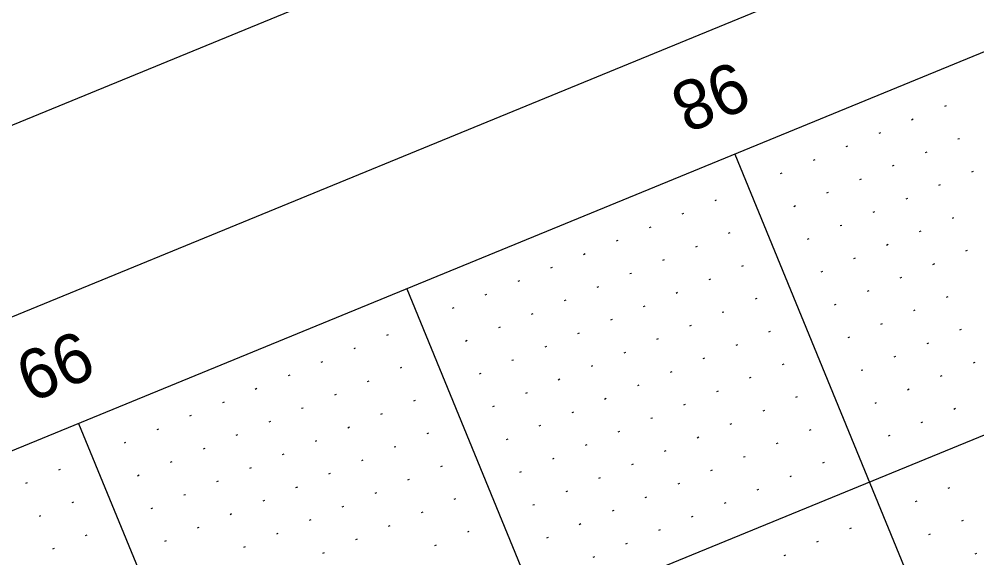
# Model space of a CAD drawing. Extents: x 2148770 to 2150891, y 142633 to 144465.
# Drawn here: x 2149616.7 to 2149751.7, y 143966.2 to 144042.2 of the extents above; entities that cross this region are included whole.
import ezdxf

# ---------------------------------------------------------------- set-up
doc = ezdxf.new("R2010")
doc.units = 0
for name, color, linetype in [('SHT_Plan_Profile_Sheet_Sta_Txt', 7, 'Continuous'), ('SHT_Plot_Shape_Half', 7, 'Continuous'), ('SHT_Profile_Grid_Major', 7, 'Continuous'), ('SHT_Profile_Grid_Minor', 7, 'Continuous'), ('SHT_Sheet_Border', 7, 'Continuous')]:
    doc.layers.add(name, color=color, linetype=linetype)

msp = doc.modelspace()

# ---------------------------------------------------------------- linework, layer by layer
at = {"layer": 'SHT_Plot_Shape_Half'}
msp.add_lwpolyline([(2150799.14, 143324.02), (2149226.52, 142678.36), (2148808.74, 143695.93), (2150381.36, 144341.59)], close=True, dxfattribs=at)
at = {"layer": 'SHT_Profile_Grid_Major'}
for p, q in [((2150326.3, 144218.99), (2148869.31, 143620.81)), ((2149717.57, 144023.12), (2149890.38, 143602.22)), ((2149671.32, 144004.13), (2149844.13, 143583.23)), ((2149625.07, 143985.14), (2149797.88, 143564.24))]:
    msp.add_line(p, q, dxfattribs=at)
at = {"layer": 'SHT_Profile_Grid_Minor'}
for p, q in [((2149747.34, 144029.94), (2149747.11, 144029.84)), ((2149742.72, 144028.04), (2149742.48, 144027.94)), ((2149738.09, 144026.14), (2149737.86, 144026.05)), ((2149733.46, 144024.24), (2149733.23, 144024.15)), ((2149749.24, 144025.31), (2149749.01, 144025.22)), ((2149744.61, 144023.41), (2149744.38, 144023.32)), ((2149728.84, 144022.34), (2149728.61, 144022.25)), ((2149739.99, 144021.52), (2149739.76, 144021.42)), ((2149724.21, 144020.44), (2149723.98, 144020.35)), ((2149751.14, 144020.69), (2149750.91, 144020.59)), ((2149735.36, 144019.62), (2149735.13, 144019.52)), ((2149746.51, 144018.79), (2149746.28, 144018.69)), ((2149730.74, 144017.72), (2149730.51, 144017.62)), ((2149714.96, 144016.65), (2149714.73, 144016.55)), ((2149741.89, 144016.89), (2149741.66, 144016.8)), ((2149710.34, 144014.75), (2149710.11, 144014.65)), ((2149726.11, 144015.82), (2149725.88, 144015.72)), ((2149737.26, 144014.99), (2149737.03, 144014.9)), ((2149748.41, 144014.16), (2149748.18, 144014.07)), ((2149705.71, 144012.85), (2149705.48, 144012.75)), ((2149732.64, 144013.09), (2149732.41, 144013)), ((2149743.79, 144012.26), (2149743.56, 144012.17)), ((2149701.09, 144010.95), (2149700.86, 144010.85)), ((2149716.86, 144012.02), (2149716.63, 144011.93)), ((2149728.01, 144011.19), (2149727.78, 144011.1)), ((2149712.24, 144010.12), (2149712.01, 144010.03)), ((2149739.16, 144010.37), (2149738.93, 144010.27)), ((2149750.31, 144009.54), (2149750.08, 144009.44)), ((2149696.46, 144009.05), (2149696.23, 144008.95)), ((2149707.61, 144008.22), (2149707.38, 144008.13)), ((2149734.54, 144008.47), (2149734.31, 144008.37)), ((2149691.84, 144007.15), (2149691.61, 144007.06)), ((2149718.76, 144007.39), (2149718.53, 144007.3)), ((2149745.69, 144007.64), (2149745.45, 144007.54)), ((2149702.99, 144006.32), (2149702.76, 144006.23)), ((2149714.14, 144005.5), (2149713.9, 144005.4)), ((2149729.91, 144006.57), (2149729.68, 144006.47)), ((2149741.06, 144005.74), (2149740.83, 144005.65)), ((2149687.21, 144005.25), (2149686.98, 144005.16)), ((2149698.36, 144004.42), (2149698.13, 144004.33)), ((2149682.59, 144003.35), (2149682.35, 144003.26)), ((2149709.51, 144003.6), (2149709.28, 144003.5)), ((2149720.66, 144002.77), (2149720.43, 144002.67)), ((2149736.44, 144003.84), (2149736.2, 144003.75)), ((2149747.59, 144003.01), (2149747.35, 144002.92)), ((2149677.96, 144001.45), (2149677.73, 144001.36)), ((2149693.74, 144002.53), (2149693.5, 144002.43)), ((2149704.89, 144001.7), (2149704.65, 144001.6)), ((2149731.81, 144001.94), (2149731.58, 144001.85)), ((2149689.11, 144000.63), (2149688.88, 144000.53)), ((2149716.04, 144000.87), (2149715.8, 144000.78)), ((2149742.96, 144001.11), (2149742.73, 144001.02)), ((2149684.49, 143998.73), (2149684.25, 143998.63)), ((2149700.26, 143999.8), (2149700.03, 143999.7)), ((2149711.41, 143998.97), (2149711.18, 143998.88)), ((2149738.33, 143999.22), (2149738.1, 143999.12)), ((2149668.71, 143997.66), (2149668.48, 143997.56)), ((2149695.63, 143997.9), (2149695.4, 143997.8)), ((2149722.56, 143998.14), (2149722.33, 143998.05)), ((2149733.71, 143997.32), (2149733.48, 143997.22)), ((2149749.48, 143998.39), (2149749.25, 143998.29)), ((2149679.86, 143996.83), (2149679.63, 143996.73)), ((2149691.01, 143996), (2149690.78, 143995.91)), ((2149706.78, 143997.07), (2149706.55, 143996.98)), ((2149717.93, 143996.25), (2149717.7, 143996.15)), ((2149744.86, 143996.49), (2149744.63, 143996.39)), ((2149664.08, 143995.76), (2149663.85, 143995.66)), ((2149702.16, 143995.17), (2149701.93, 143995.08)), ((2149740.23, 143994.59), (2149740, 143994.5)), ((2149659.46, 143993.86), (2149659.23, 143993.76)), ((2149686.38, 143994.1), (2149686.15, 143994.01)), ((2149697.53, 143993.27), (2149697.3, 143993.18)), ((2149713.31, 143994.35), (2149713.08, 143994.25)), ((2149724.46, 143993.52), (2149724.23, 143993.42)), ((2149751.38, 143993.76), (2149751.15, 143993.67)), ((2149654.83, 143991.96), (2149654.6, 143991.86)), ((2149670.61, 143993.03), (2149670.38, 143992.94)), ((2149681.76, 143992.2), (2149681.53, 143992.11)), ((2149708.68, 143992.45), (2149708.45, 143992.35)), ((2149735.61, 143992.69), (2149735.38, 143992.6)), ((2149746.76, 143991.86), (2149746.53, 143991.77)), ((2149665.98, 143991.13), (2149665.75, 143991.04)), ((2149692.91, 143991.38), (2149692.68, 143991.28)), ((2149704.06, 143990.55), (2149703.83, 143990.45)), ((2149719.83, 143991.62), (2149719.6, 143991.52)), ((2149650.21, 143990.06), (2149649.98, 143989.96)), ((2149661.36, 143989.23), (2149661.13, 143989.14)), ((2149688.28, 143989.48), (2149688.05, 143989.38)), ((2149715.21, 143989.72), (2149714.98, 143989.63)), ((2149742.13, 143989.97), (2149741.9, 143989.87)), ((2149645.58, 143988.16), (2149645.35, 143988.07)), ((2149672.51, 143988.4), (2149672.28, 143988.31)), ((2149699.43, 143988.65), (2149699.2, 143988.55)), ((2149710.58, 143987.82), (2149710.35, 143987.73)), ((2149726.36, 143988.89), (2149726.13, 143988.8)), ((2149737.51, 143988.07), (2149737.28, 143987.97)), ((2149656.73, 143987.33), (2149656.5, 143987.24)), ((2149667.88, 143986.51), (2149667.65, 143986.41)), ((2149683.66, 143987.58), (2149683.43, 143987.48)), ((2149694.81, 143986.75), (2149694.58, 143986.66)), ((2149721.73, 143986.99), (2149721.5, 143986.9)), ((2149748.66, 143987.24), (2149748.43, 143987.14)), ((2149640.96, 143986.26), (2149640.73, 143986.17)), ((2149652.11, 143985.43), (2149651.88, 143985.34)), ((2149705.96, 143985.92), (2149705.73, 143985.83)), ((2149717.11, 143985.1), (2149716.88, 143985)), ((2149744.03, 143985.34), (2149743.8, 143985.25)), ((2149636.33, 143984.36), (2149636.1, 143984.27)), ((2149663.26, 143984.61), (2149663.03, 143984.51)), ((2149674.41, 143983.78), (2149674.18, 143983.68)), ((2149690.18, 143984.85), (2149689.95, 143984.76)), ((2149701.33, 143984.02), (2149701.1, 143983.93)), ((2149728.26, 143984.27), (2149728.03, 143984.17)), ((2149631.71, 143982.46), (2149631.48, 143982.37)), ((2149647.48, 143983.54), (2149647.25, 143983.44)), ((2149658.63, 143982.71), (2149658.4, 143982.61)), ((2149685.56, 143982.95), (2149685.33, 143982.86)), ((2149712.48, 143983.2), (2149712.25, 143983.1)), ((2149723.63, 143982.37), (2149723.4, 143982.27)), ((2149739.41, 143983.44), (2149739.17, 143983.35)), ((2149642.86, 143981.64), (2149642.63, 143981.54)), ((2149669.78, 143981.88), (2149669.55, 143981.79)), ((2149696.71, 143982.12), (2149696.48, 143982.03)), ((2149707.86, 143981.3), (2149707.62, 143981.2)), ((2149638.23, 143979.74), (2149638, 143979.64)), ((2149654.01, 143980.81), (2149653.78, 143980.71)), ((2149665.16, 143979.98), (2149664.93, 143979.89)), ((2149692.08, 143980.23), (2149691.85, 143980.13)), ((2149719.01, 143980.47), (2149718.77, 143980.38)), ((2149730.16, 143979.64), (2149729.92, 143979.55)), ((2149622.46, 143978.67), (2149622.23, 143978.57)), ((2149649.38, 143978.91), (2149649.15, 143978.81)), ((2149676.31, 143979.15), (2149676.07, 143979.06)), ((2149687.46, 143978.33), (2149687.22, 143978.23)), ((2149703.23, 143979.4), (2149703, 143979.3)), ((2149714.38, 143978.57), (2149714.15, 143978.48)), ((2149633.61, 143977.84), (2149633.38, 143977.74)), ((2149644.76, 143977.01), (2149644.52, 143976.92)), ((2149660.53, 143978.08), (2149660.3, 143977.99)), ((2149671.68, 143977.26), (2149671.45, 143977.16)), ((2149698.61, 143977.5), (2149698.37, 143977.4)), ((2149725.53, 143977.74), (2149725.3, 143977.65)), ((2149617.83, 143976.77), (2149617.6, 143976.67)), ((2149655.91, 143976.18), (2149655.67, 143976.09)), ((2149693.98, 143975.6), (2149693.75, 143975.51)), ((2149709.76, 143976.67), (2149709.52, 143976.58)), ((2149720.9, 143975.84), (2149720.67, 143975.75)), ((2149747.83, 143976.09), (2149747.6, 143975.99)), ((2149640.13, 143975.11), (2149639.9, 143975.02)), ((2149651.28, 143974.28), (2149651.05, 143974.19)), ((2149667.06, 143975.36), (2149666.82, 143975.26)), ((2149678.2, 143974.53), (2149677.97, 143974.43)), ((2149705.13, 143974.77), (2149704.9, 143974.68)), ((2149624.36, 143974.04), (2149624.12, 143973.95)), ((2149635.51, 143973.21), (2149635.27, 143973.12)), ((2149662.43, 143973.46), (2149662.2, 143973.36)), ((2149689.35, 143973.7), (2149689.12, 143973.61)), ((2149716.28, 143973.95), (2149716.05, 143973.85)), ((2149743.2, 143974.19), (2149742.97, 143974.1)), ((2149619.73, 143972.14), (2149619.5, 143972.05)), ((2149646.65, 143972.39), (2149646.42, 143972.29)), ((2149657.8, 143971.56), (2149657.57, 143971.46)), ((2149673.58, 143972.63), (2149673.35, 143972.53)), ((2149700.5, 143972.87), (2149700.27, 143972.78)), ((2149711.65, 143972.05), (2149711.42, 143971.95)), ((2149642.03, 143970.49), (2149641.8, 143970.39)), ((2149668.95, 143970.73), (2149668.72, 143970.64)), ((2149695.88, 143970.98), (2149695.65, 143970.88)), ((2149733.95, 143970.39), (2149733.72, 143970.3)), ((2149749.73, 143971.46), (2149749.5, 143971.37)), ((2149626.25, 143969.41), (2149626.02, 143969.32)), ((2149653.18, 143969.66), (2149652.95, 143969.56)), ((2149680.1, 143969.9), (2149679.87, 143969.81)), ((2149691.25, 143969.08), (2149691.02, 143968.98)), ((2149707.03, 143970.15), (2149706.8, 143970.05)), ((2149745.1, 143969.56), (2149744.87, 143969.47)), ((2149621.63, 143967.52), (2149621.4, 143967.42)), ((2149637.4, 143968.59), (2149637.17, 143968.49)), ((2149648.55, 143967.76), (2149648.32, 143967.67)), ((2149664.33, 143968.83), (2149664.1, 143968.74)), ((2149675.48, 143968), (2149675.25, 143967.91)), ((2149702.4, 143968.25), (2149702.17, 143968.15)), ((2149729.33, 143968.49), (2149729.1, 143968.4)), ((2149659.7, 143966.93), (2149659.47, 143966.84)), ((2149697.78, 143966.35), (2149697.55, 143966.25)), ((2149724.7, 143966.59), (2149724.47, 143966.5)), ((2149751.63, 143966.84), (2149751.4, 143966.74))]:
    msp.add_line(p, q, dxfattribs=at)
at = {"layer": 'SHT_Sheet_Border'}
msp.add_line((2150307.31, 144265.25), (2149093.15, 143766.76), dxfattribs=at)
msp.add_lwpolyline([(2150699.45, 143310.11), (2149242.47, 142711.93), (2148843.68, 143683.25), (2150300.66, 144281.43)], close=True, dxfattribs=at)

# ---------------------------------------------------------------- texts
at = {"layer": 'SHT_Plan_Profile_Sheet_Sta_Txt'}
for s, p in [('98', (2149717.68, 144036.41)), ('99', (2149625.25, 143998.46))]:
    msp.add_text(s, height=7, rotation=202.3213, dxfattribs=at).set_placement(p)

doc.saveas('drawing.dxf')
